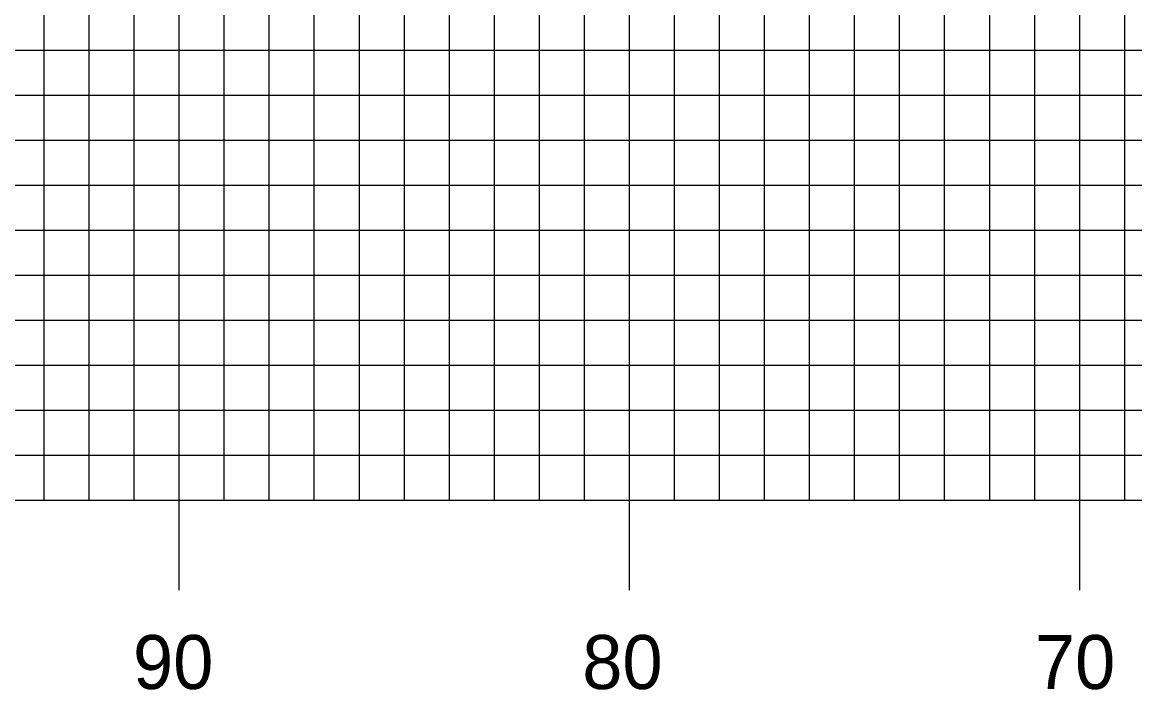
# Model space of a CAD drawing. Extents: x 1770842 to 1771185, y 442591 to 442811.
# Drawn here: x 1770914.07 to 1770938.78, y 442709.45 to 442724.29 of the extents above; entities that cross this region are included whole.
import ezdxf

# ---------------------------------------------------------------- set-up
doc = ezdxf.new("R2010")
doc.units = 0
for name, color, linetype in [('H_V ANNOTATION', 7, 'Continuous'), ('MAJOR', 7, 'Continuous'), ('MINOR', 7, 'Continuous')]:
    doc.layers.add(name, color=color, linetype=linetype)

msp = doc.modelspace()

# ---------------------------------------------------------------- linework, layer by layer
at = {"layer": 'MAJOR'}
for p, q in [((1770917.554, 442713.665), (1770917.554, 442738.665)), ((1770927.554, 442713.665), (1770927.554, 442738.665)), ((1770937.554, 442713.665), (1770937.554, 442738.665)), ((1770867.554, 442723.665), (1771147.554, 442723.665)), ((1770867.554, 442718.665), (1771147.554, 442718.665)), ((1770867.554, 442713.665), (1771147.554, 442713.665)), ((1770867.554, 442713.665), (1771147.554, 442713.665)), ((1770917.554, 442711.661), (1770917.554, 442713.665)), ((1770927.554, 442711.661), (1770927.554, 442713.665)), ((1770937.554, 442711.661), (1770937.554, 442713.665))]:
    msp.add_line(p, q, dxfattribs=at)
at = {"layer": 'MINOR'}
for p, q in [((1770914.554, 442713.665), (1770914.554, 442738.665)), ((1770915.554, 442713.665), (1770915.554, 442738.665)), ((1770916.554, 442713.665), (1770916.554, 442738.665)), ((1770918.554, 442713.665), (1770918.554, 442738.665)), ((1770919.554, 442713.665), (1770919.554, 442738.665)), ((1770920.554, 442713.665), (1770920.554, 442738.665)), ((1770921.554, 442713.665), (1770921.554, 442738.665)), ((1770922.554, 442713.665), (1770922.554, 442738.665)), ((1770923.554, 442713.665), (1770923.554, 442738.665)), ((1770924.554, 442713.665), (1770924.554, 442738.665)), ((1770925.554, 442713.665), (1770925.554, 442738.665)), ((1770926.554, 442713.665), (1770926.554, 442738.665)), ((1770928.554, 442713.665), (1770928.554, 442738.665)), ((1770929.554, 442713.665), (1770929.554, 442738.665)), ((1770930.554, 442713.665), (1770930.554, 442738.665)), ((1770931.554, 442713.665), (1770931.554, 442738.665)), ((1770932.554, 442713.665), (1770932.554, 442738.665)), ((1770933.554, 442713.665), (1770933.554, 442738.665)), ((1770934.554, 442713.665), (1770934.554, 442738.665)), ((1770935.554, 442713.665), (1770935.554, 442738.665)), ((1770936.554, 442713.665), (1770936.554, 442738.665)), ((1770938.554, 442713.665), (1770938.554, 442738.665)), ((1770867.554, 442722.665), (1771147.554, 442722.665)), ((1770867.554, 442721.665), (1771147.554, 442721.665)), ((1770867.554, 442720.665), (1771147.554, 442720.665)), ((1770867.554, 442719.665), (1771147.554, 442719.665)), ((1770867.554, 442717.665), (1771147.554, 442717.665)), ((1770867.554, 442716.665), (1771147.554, 442716.665)), ((1770867.554, 442715.665), (1771147.554, 442715.665)), ((1770867.554, 442714.665), (1771147.554, 442714.665))]:
    msp.add_line(p, q, dxfattribs=at)

# ---------------------------------------------------------------- texts
at = {"layer": 'H_V ANNOTATION'}
for s, p in [('90', (1770916.527, 442709.465)), ('80', (1770926.505, 442709.465)), ('70', (1770936.558, 442709.465))]:
    msp.add_text(s, height=1.2, dxfattribs=at).set_placement(p)

doc.saveas('drawing.dxf')
